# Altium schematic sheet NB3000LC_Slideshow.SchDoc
size A; DocumentNumber: 1; SheetNumber: 1; SheetTotal: 1
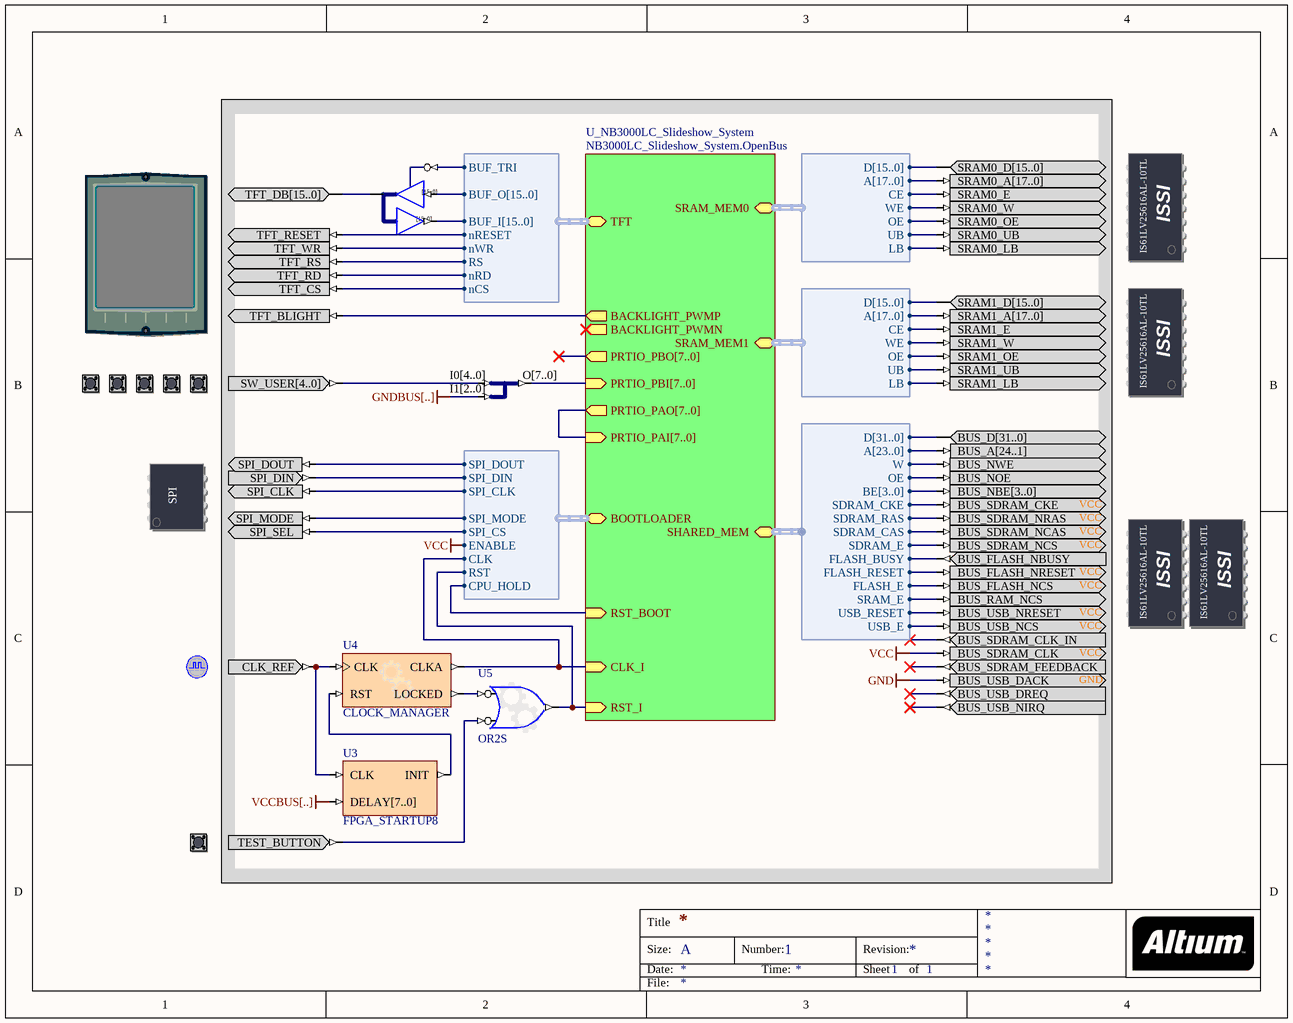
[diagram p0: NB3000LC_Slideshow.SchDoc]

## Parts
(Parts that share a designator on the sheet are numbered #1, #2 ... from top to bottom, then left to right.)
?#1  SRAM0  (value not drawn)
?#2  TFT_LCD  (value not drawn)
?#3  SRAM1  (value not drawn)
?#4  USER_BUTTONS  (value not drawn)
?#5  SHARED_SRAM  (value not drawn)
?#6  SERIALFMEMORY  (value not drawn)
?#7  CLOCK_REFERENCE  (value not drawn)
?#8  TEST_BUTTON  (value not drawn)
U1  IOBUF16B  (value not drawn)
U2  BUS_JS  (value not drawn)
U3  FPGA_STARTUP8
U4  CLOCK_MANAGER
U5  OR2S

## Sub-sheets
U_NB3000LC_Slideshow_System = NB3000LC_Slideshow_System.OpenBus: CLK_I (in), RST_I (in), PRTIO_PAO[7..0] (out, harness VGA32_ILI9320), PRTIO_PAI[7..0] (in, harness VGA32_ILI9320), PRTIO_PBO[7..0] (out), PRTIO_PBI[7..0] (in), SRAM_MEM0 (harness WB_MEM_CTRL_SRAM16_A18), SRAM_MEM1 (harness WB_MEM_CTRL_SRAM16_A18), BACKLIGHT_PWMN (out), BACKLIGHT_PWMP (out), BOOTLOADER (harness WB_BOOTLOADER), RST_BOOT (in), SHARED_MEM (harness WB_SHARED_MEM_CTRL), TFT (harness VGA32_ILI9320)

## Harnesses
WB_MEM_CTRL_SRAM16_A18: D[15..0], A[17..0], CE, WE, OE, UB, LB
WB_BOOTLOADER: SPI_DOUT, SPI_DIN, SPI_CLK, SPI_MODE, SPI_CS, CLK, RST, ENABLE, CPU_HOLD
WB_SHARED_MEM_CTRL: D[31..0], A[23..0], W, OE, BE[3..0], SDRAM_CKE, SDRAM_RAS, SDRAM_CAS, SDRAM_E, FLASH_BUSY, FLASH_RESET, FLASH_E, SRAM_E, USB_RESET, USB_E
VGA32_ILI9320: BUF_TRI, BUF_O[15..0], BUF_I[15..0], nRESET, nWR, RS, nRD, nCS

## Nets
GND: ?#5.BUS_USB_DACK
VCC: ?#5.BUS_SDRAM_CLK ; sheet U_NB3000LC_Slideshow_System/BOOTLOADER.ENABLE
VCCBUS[..]: U3.DELAY[7..0]
Net?#1_SRAM0_E: ?#1.SRAM0_E ; sheet U_NB3000LC_Slideshow_System/SRAM_MEM0.CE
Net?#1_SRAM0_LB: ?#1.SRAM0_LB ; sheet U_NB3000LC_Slideshow_System/SRAM_MEM0.LB
Net?#1_SRAM0_OE: ?#1.SRAM0_OE ; sheet U_NB3000LC_Slideshow_System/SRAM_MEM0.OE
Net?#1_SRAM0_UB: ?#1.SRAM0_UB ; sheet U_NB3000LC_Slideshow_System/SRAM_MEM0.UB
Net?#1_SRAM0_W: ?#1.SRAM0_W ; sheet U_NB3000LC_Slideshow_System/SRAM_MEM0.WE
Net?#2_TFT_BLIGHT: ?#2.TFT_BLIGHT ; sheet U_NB3000LC_Slideshow_System/BACKLIGHT_PWMP
Net?#2_TFT_CS: ?#2.TFT_CS ; sheet U_NB3000LC_Slideshow_System/TFT.nCS
Net?#2_TFT_RD: ?#2.TFT_RD ; sheet U_NB3000LC_Slideshow_System/TFT.nRD
Net?#2_TFT_RESET: ?#2.TFT_RESET ; sheet U_NB3000LC_Slideshow_System/TFT.nRESET
Net?#2_TFT_RS: ?#2.TFT_RS ; sheet U_NB3000LC_Slideshow_System/TFT.RS
Net?#2_TFT_WR: ?#2.TFT_WR ; sheet U_NB3000LC_Slideshow_System/TFT.nWR
Net?#3_SRAM1_E: ?#3.SRAM1_E ; sheet U_NB3000LC_Slideshow_System/SRAM_MEM1.CE
Net?#3_SRAM1_LB: ?#3.SRAM1_LB ; sheet U_NB3000LC_Slideshow_System/SRAM_MEM1.LB
Net?#3_SRAM1_OE: ?#3.SRAM1_OE ; sheet U_NB3000LC_Slideshow_System/SRAM_MEM1.OE
Net?#3_SRAM1_UB: ?#3.SRAM1_UB ; sheet U_NB3000LC_Slideshow_System/SRAM_MEM1.UB
Net?#3_SRAM1_W: ?#3.SRAM1_W ; sheet U_NB3000LC_Slideshow_System/SRAM_MEM1.WE
Net?#5_BUS_FLASH_NBUSY: ?#5.BUS_FLASH_NBUSY ; sheet U_NB3000LC_Slideshow_System/SHARED_MEM.FLASH_BUSY
Net?#5_BUS_FLASH_NCS: ?#5.BUS_FLASH_NCS ; sheet U_NB3000LC_Slideshow_System/SHARED_MEM.FLASH_E
Net?#5_BUS_FLASH_NRESET: ?#5.BUS_FLASH_NRESET ; sheet U_NB3000LC_Slideshow_System/SHARED_MEM.FLASH_RESET
Net?#5_BUS_NOE: ?#5.BUS_NOE ; sheet U_NB3000LC_Slideshow_System/SHARED_MEM.OE
Net?#5_BUS_NWE: ?#5.BUS_NWE ; sheet U_NB3000LC_Slideshow_System/SHARED_MEM.W
Net?#5_BUS_RAM_NCS: ?#5.BUS_RAM_NCS ; sheet U_NB3000LC_Slideshow_System/SHARED_MEM.SRAM_E
Net?#5_BUS_SDRAM_CKE: ?#5.BUS_SDRAM_CKE ; sheet U_NB3000LC_Slideshow_System/SHARED_MEM.SDRAM_CKE
Net?#5_BUS_SDRAM_NCAS: ?#5.BUS_SDRAM_NCAS ; sheet U_NB3000LC_Slideshow_System/SHARED_MEM.SDRAM_CAS
Net?#5_BUS_SDRAM_NCS: ?#5.BUS_SDRAM_NCS ; sheet U_NB3000LC_Slideshow_System/SHARED_MEM.SDRAM_E
Net?#5_BUS_SDRAM_NRAS: ?#5.BUS_SDRAM_NRAS ; sheet U_NB3000LC_Slideshow_System/SHARED_MEM.SDRAM_RAS
Net?#5_BUS_USB_NCS: ?#5.BUS_USB_NCS ; sheet U_NB3000LC_Slideshow_System/SHARED_MEM.USB_E
Net?#5_BUS_USB_NRESET: ?#5.BUS_USB_NRESET ; sheet U_NB3000LC_Slideshow_System/SHARED_MEM.USB_RESET
Net?#6_SPI_CLK: ?#6.SPI_CLK ; sheet U_NB3000LC_Slideshow_System/BOOTLOADER.SPI_CLK
Net?#6_SPI_DIN: ?#6.SPI_DIN ; sheet U_NB3000LC_Slideshow_System/BOOTLOADER.SPI_DIN
Net?#6_SPI_DOUT: ?#6.SPI_DOUT ; sheet U_NB3000LC_Slideshow_System/BOOTLOADER.SPI_DOUT
Net?#6_SPI_MODE: ?#6.SPI_MODE ; sheet U_NB3000LC_Slideshow_System/BOOTLOADER.SPI_MODE
Net?#6_SPI_SEL: ?#6.SPI_SEL ; sheet U_NB3000LC_Slideshow_System/BOOTLOADER.SPI_CS
Net?#7_CLK_REF: ?#7.CLK_REF U3.CLK U4.CLK
Net?#8_TEST_BUTTON: ?#8.TEST_BUTTON U5.I1
NetU1_T: U1.T ; sheet U_NB3000LC_Slideshow_System/TFT.BUF_TRI
NetU3_INIT: U3.INIT U4.RST
NetU4_CLKA: U4.CLKA ; sheet U_NB3000LC_Slideshow_System/CLK_I, sheet U_NB3000LC_Slideshow_System/BOOTLOADER.CLK
NetU4_LOCKED: U4.LOCKED U5.I0
NetU5_O: U5.O ; sheet U_NB3000LC_Slideshow_System/RST_I, sheet U_NB3000LC_Slideshow_System/BOOTLOADER.RST
(unnamed): sheet U_NB3000LC_Slideshow_System/RST_BOOT, sheet U_NB3000LC_Slideshow_System/BOOTLOADER.CPU_HOLD

Not connected (* = marked no-connect by the designer): ?#1 SRAM0_A[17..0] SRAM0_D[15..0]; ?#2 TFT_DB[15..0]; ?#3 SRAM1_A[17..0] SRAM1_D[15..0]; ?#4 SW_USER[4..0]; ?#5 BUS_A[24..1] BUS_D[31..0] BUS_NBE[3..0] BUS_SDRAM_CLK_IN* BUS_SDRAM_FEEDBACK* BUS_USB_DREQ* BUS_USB_NIRQ*; U1 I[15..0] IO[15..0] O[15..0]; U2 I0[4..0] I1[2..0] O[7..0]

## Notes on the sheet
- Labels drawn without touching a wire or pin: GNDBUS[..]

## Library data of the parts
?#1 = SRAM0: Free Static RAM - Daughterboard; PortComponent: True
?#2 = TFT_LCD: TFT LCD Panel; PortComponent: True
?#3 = SRAM1: Free Static RAM - Daughterboard; PortComponent: True
?#4 = USER_BUTTONS: Generic User Buttons; PortComponent: True
?#5 = SHARED_SRAM: Common-Bus SRAM; PortComponent: True
?#6 = SPI_BUS: Serial SPI Flash RAM; PortComponent: True
?#7 = CLOCK_REFERENCE: Global System Clock Reference Supply; PortComponent: True
?#8 = TEST_BUTTON: Test / Reset Button; PortComponent: True
U1 = IOBUF16B: 16-Bit Input/Output Buffer, Bus Version; SubClass: IOBUF; Enable: Low; Control: Common Control T; PortSize: 16; ArchiveName: GENERIC; VHDLIB_SIM: GENERIC_LIB
U2 = BUS_JS: Configurable Bus Joiner/Splitter; ConfiguratorName: GENERIC_BUS_JS; ConfigurationParameters: {}Version[1.0]{}SplitterJoinerType[Joiner]{}SignalCount[2]{}SignalWidth0[5]{}SignalWidth1[3]{}
U3 = FPGA_STARTUP8: FPGA Startup With 8 Bit Delay
U4 = CLOCKMANAGER: Configurable Clock Manager; ConfiguratorName: GENERIC_CLOCKMANAGER; ConfigurationParameters: {}Version[1.0]{}Option_Configuration[object _1: TClockManagerPersist / VersionMajor [ 0 / VersionMinor [ 0 / InputFreq [ 20.000000000000000000 / InputName [ 'CLK' / OutputTargets [ < / item / Name [ 'CLKA' / OutFreqMin [ 40.000000000000000000 / OutFreqMax [ 40.000000000000000000 / OutPostDivider [ 1.000000000000000000 / end> / OutputDevices [ < / item / Name [ 'Spartan3AN' / Valid [ True / OutputActuals [ < / item / Name [ 'CLK0' / Multipler [ 1.000000000000000000 / Divider [ 1.000000000000000000 / OutFreq [ 20.000000000000000000 / OutputMap [ 1 / end / item / Name [ 'CLK90' / Multipler [ 1.000000000000000000 / Divider [ 1.000000000000000000 / OutPhase [ 90.000000000000000000 / OutFreq [ 20.000000000000000000 / OutputMap [ 2 / end / item / Name [ 'CLK180' / Multipler [ 1.000000000000000000 / Divider [ 1.000000000000000000 / OutPhase [ 180.000000000000000000 / OutFreq [ 20.000000000000000000 / OutputMap [ 3 / end / item / Name [ 'CLK270' / Multipler [ 1.000000000000000000 / Divider [ 1.000000000000000000 / OutPhase [ 270.000000000000000000 / OutFreq [ 20.000000000000000000 / OutputMap [ 4 / end / item / Name [ 'CLK2X' / Multipler [ 2.000000000000000000 / Divider [ 1.000000000000000000 / OutFreq [ 40.000000000000000000 / OutputMap [ 5 / end / item / Name [ 'CLKDV' / Multipler [ 1.000000000000000000 / Divider [ 16.000000000000000000 / OutFreq [ 1.250000000000000000 / OutputMap [ 6 / end / item / Name [ 'CLK2X180' / Multipler [ 1.000000000000000000 / Divider [ 1.000000000000000000 / OutPhase [ 180.000000000000000000 / OutFreq [ 40.000000000000000000 / OutputMap [ 7 / end / item / Name [ 'CLKFX' / Multipler [ 5.000000000000000000 / Divider [ 2.000000000000000000 / OutFreq [ 50.000000000000000000 / OutputMap [ 0 / end / item / Name [ 'CLKFX180' / Multipler [ 1.000000000000000000 / Divider [ 1.000000000000000000 / OutPhase [ 180.000000000000000000 / OutFreq [ 50.000000000000000000 / OutputMap [ 8 / end> / InternalActuals [ <> / CustomVars [ <> / end / item / Name [ 'Cyclone3' / Valid [ True / OutputActuals [ < / item / Name [ 'C0' / Multipler [ 5.000000000000000000 / Divider [ 2.000000000000000000 / OutFreq [ 50.000000000000000000 / OutputMap [ 0 / end / item / Name [ 'C1' / Multipler [ 1.000000000000000000 / Divider [ 1.000000000000000000 / OutFreq [ 20.000000000000000000 / OutputMap [ 1 / end / item / Name [ 'C2' / Multipler [ 1.000000000000000000 / Divider [ 1.000000000000000000 / OutFreq [ 20.000000000000000000 / OutputMap [ 2 / end / item / Name [ 'C3' / Multipler [ 1.000000000000000000 / Divider [ 1.000000000000000000 / OutFreq [ 20.000000000000000000 / OutputMap [ 3 / end / item / Name [ 'C4' / Multipler [ 1.000000000000000000 / Divider [ 1.000000000000000000 / OutFreq [ 20.000000000000000000 / OutputMap [ 4 / end> / InternalActuals [ <> / CustomVars [ <> / end / item / Name [ 'ECP2' / Valid [ True / OutputActuals [ < / item / Name [ 'CLKOP' / Multipler [ 2.000000000000000000 / Divider [ 1.000000000000000000 / OutFreq [ 40.000000000000000000 / OutputMap [ 0 / end / item / Name [ 'CLKOS' / Multipler [ 1.000000000000000000 / Divider [ 1.000000000000000000 / OutFreq [ 40.000000000000000000 / OutputMap [ 1 / end / item / Name [ 'CLKOK' / Multipler [ 1.000000000000000000 / Divider [ 2.000000000000000000 / OutFreq [ 20.000000000000000000 / OutputMap [ 2 / end> / InternalActuals [ <> / CustomVars [ <> / end> / MinInputFreq [ 2.000000000000000000 / MaxInputFreq [ 420.000000000000000000 / MinOutputFreq [ 2.000000000000000000 / MaxOutputFreq [ 420.000000000000000000 / MaxOutputCount [ 3 / end]{}
U5 = GATE: Configurable Generic Gate; ConfiguratorName: GENERIC_GATE; ConfigurationParameters: {}Version[1.1]{}GateKind[OR]{}BusInput[False]{}GateInputType[Bit]{}GateOutputOption[Normal]{}BusWidth[8]{}RegisterOutputs[False]{}NegativeClockEdge[False]{}InputCount[2]{}InputInvert0[True]{}InputInvert1[True]{}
